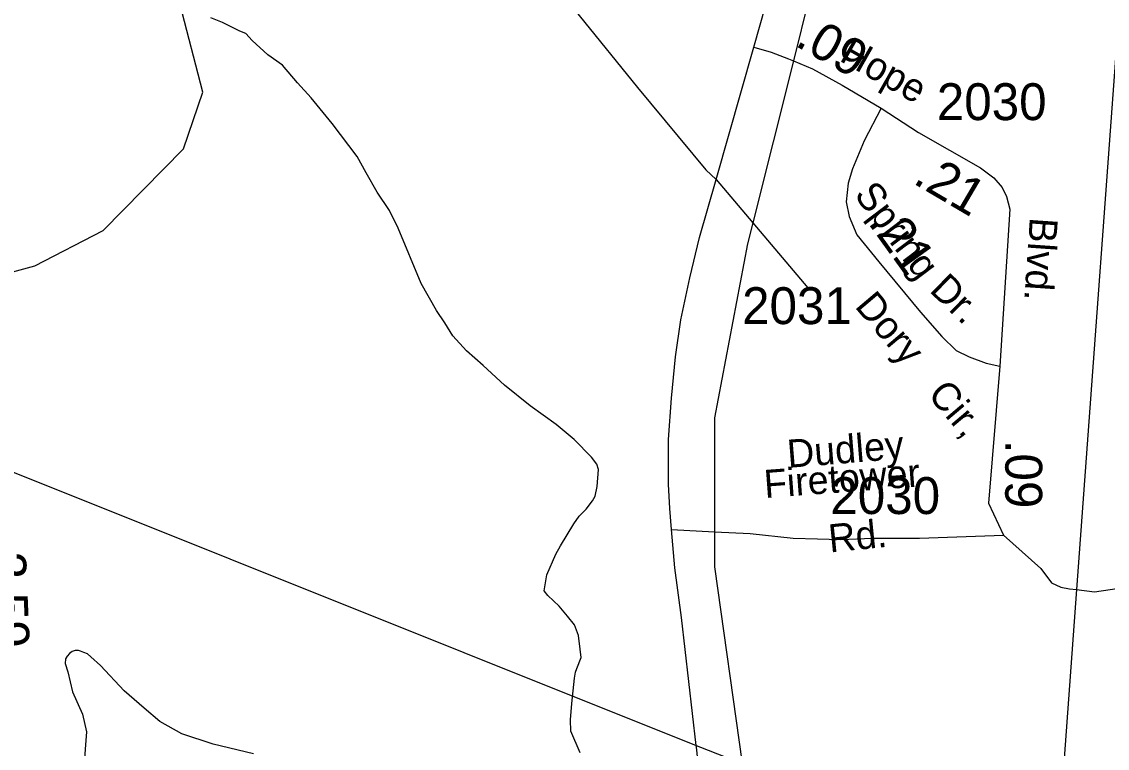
# Model space of a CAD drawing. Extents: x 2206922 to 2357709, y 510027 to 673830.
# Drawn here: x 2284540 to 2288216, y 564319 to 566780 of the extents above; entities that cross this region are included whole.
import ezdxf

# ---------------------------------------------------------------- set-up
doc = ezdxf.new("R2010")
doc.units = 0
for name, color, linetype in [('Exist Boundary Political Urban Extension UEB', 7, 'Continuous'), ('Exist Hydrographic Creek Single Shore', 7, 'Continuous'), ('Exist Hydrographic Misc Water Feature', 7, 'Continuous'), ('Exist Railroad Mainline', 7, 'Continuous'), ('Exist Road Non-System Type 51', 7, 'Continuous'), ('Exist Road Non-System Type 51 Label', 7, 'Continuous'), ('Exist Road Primary US Attributed', 7, 'Continuous'), ('Exist Road Primary US Mileage Hundredths English Label', 7, 'Continuous'), ('Exist Road Secondary Mileage Hundredths English Label', 7, 'Continuous'), ('Exist Road Secondary Type 51 Attributed', 7, 'Continuous'), ('Exist Road Secondary Type 51 Label', 7, 'Continuous'), ('Exist Road Secondary Type 51 Number Label', 7, 'Continuous'), ('Exist Utilities Electrical Transmission Line', 7, 'Continuous')]:
    doc.layers.add(name, color=color, linetype=linetype)

msp = doc.modelspace()

# ---------------------------------------------------------------- linework, layer by layer
at = {"layer": 'Exist Boundary Political Urban Extension UEB'}
for p, q in [((2287255.6, 567057.4), (2287153.1, 566647.3)), ((2287153.1, 566647.3), (2287015.8, 566098.4))]:
    msp.add_line(p, q, dxfattribs=at)
for points in [[(2287015.8, 566098.4), (2286997.9, 566026.9), (2286885.9, 565438.5), (2286885.9, 565052.4)], [(2286885.9, 565052.4), (2286885.9, 564934.1), (2286979.2, 564267.7)]]:
    msp.add_lwpolyline(points, dxfattribs=at)
at = {"layer": 'Exist Hydrographic Creek Single Shore'}
msp.add_lwpolyline([(2284267.9, 565867.3), (2284583.9, 565952.8), (2284815.8, 566072.7), (2285087.9, 566349.2), (2285152.9, 566541.4), (2285074.8, 566841.4), (2284622.9, 567145.7), (2284546.8, 567245.7), (2284511.9, 567393.9), (2284584.9, 567602.4), (2284716.8, 567786.6), (2285051.8, 568416.1), (2285341.8, 568610.2), (2286260.8, 569116.4), (2286583.8, 569362.4), (2286847.9, 569612.9), (2287119.8, 569968.2), (2287160, 570075.5)], dxfattribs=at)
at = {"layer": 'Exist Hydrographic Misc Water Feature'}
msp.add_lwpolyline([(2286430.6, 564303.6), (2286399.8, 564377.2), (2286397.8, 564415.2), (2286402.7, 564471.2), (2286411.9, 564557), (2286415.6, 564577.1), (2286419.9, 564589.1), (2286433.9, 564627.1), (2286431.2, 564655), (2286424.8, 564701), (2286412.1, 564737), (2286388.1, 564766.5), (2286359.8, 564800.4), (2286321.5, 564836.2), (2286309.2, 564851.8), (2286318.6, 564906), (2286348.2, 564976.2), (2286363.9, 565004.6), (2286409.1, 565078.9), (2286427.1, 565105), (2286451.1, 565129), (2286472.4, 565157.4), (2286482.3, 565173.3), (2286488, 565205.3), (2286493.3, 565263.3), (2286487.4, 565281.2), (2286469.3, 565305), (2286410.7, 565364.5), (2286350, 565415.8), (2286261.6, 565479.1), (2286174.9, 565548.5), (2286102.3, 565615.4), (2286045.9, 565664.8), (2285999.4, 565716.4), (2285972.9, 565760.2), (2285944.6, 565802.2), (2285891.9, 565893.6), (2285814.2, 566080.5), (2285785.5, 566140.4), (2285743, 566202), (2285706.3, 566267.5), (2285675.6, 566323.2), (2285590.9, 566434.5), (2285520, 566521.4), (2285473.6, 566573), (2285423.2, 566632.5), (2285373.1, 566668), (2285320.6, 566715.7), (2285298.3, 566739.4), (2285277.8, 566747.3), (2285220, 566776.7), (2285180, 566792.5)], dxfattribs=at)
at = {"layer": 'Exist Railroad Mainline'}
msp.add_lwpolyline([(2288952.5, 575417.9), (2288939.4, 575328.9), (2288894.6, 575010.5), (2288861, 574754.3), (2288832.1, 574422.3), (2288797.4, 574086.4), (2288738.9, 573282.2), (2288399.4, 568789.4), (2288395.5, 568735.1), (2288273, 567057.4), (2288112.4, 564856.3), (2288039.1, 563851.4), (2288038, 563836.6), (2287853.8, 561437.5), (2287845.7, 561332.3), (2287845.6, 561330.8)], dxfattribs=at)
at = {"layer": 'Exist Road Non-System Type 51'}
for p, q in [((2286891.3, 566245.8), (2287015.8, 566098.4)), ((2287015.8, 566098.4), (2287201.8, 565878.3)), ((2286740.1, 565060), (2286885.9, 565052.4))]:
    msp.add_line(p, q, dxfattribs=at)
for points in [[(2286229.7, 567046), (2286625.6, 566557), (2286857.1, 566278), (2286891.3, 566245.8)], [(2286885.9, 565052.4), (2287006.4, 565046.2), (2287152.4, 565030.4), (2287235.3, 565028.4), (2287314.2, 565026.4), (2287420.8, 565030.4), (2287580.6, 565030.4), (2287864.7, 565041.2)], [(2287864.7, 565041.2), (2287991.7, 564928.2), (2288027.2, 564878.9), (2288058.8, 564865.1), (2288088.4, 564859.1), (2288112.4, 564856.3)], [(2288112.4, 564856.3), (2288173.2, 564849.3), (2288416.1, 564885.6)], [(2285324.2, 564300.5), (2285188.1, 564333), (2285081.6, 564368.6), (2285007.6, 564410), (2284954.3, 564454.5), (2284886.2, 564513.7), (2284806.3, 564599.5), (2284773.8, 564629.2), (2284761.9, 564638.5), (2284750.1, 564643.9), (2284738.8, 564648.3), (2284731.5, 564650.3), (2284720.2, 564650.3), (2284709.9, 564646.3), (2284701.5, 564640.4), (2284693.2, 564631.6), (2284687.3, 564621.8), (2284686.3, 564606.5), (2284695.2, 564577.6), (2284711.8, 564510.3), (2284745.7, 564434.2), (2284759, 564374.5), (2284750.1, 564256.1)]]:
    msp.add_lwpolyline(points, dxfattribs=at)
at = {"layer": 'Exist Road Primary US Attributed'}
for points in [[(2287018.9, 566693.9), (2287122, 567057.4), (2287159.7, 567190.1), (2287281, 567619.5), (2287342.7, 567854), (2287396.4, 568031.7), (2287443.8, 568215.9), (2287480.6, 568403.5), (2287496.4, 568528.5), (2287500.3, 568606.2), (2287505.6, 568701.6), (2287512.2, 568832.5)], [(2287157.1, 561422.2), (2287066.4, 562197.1), (2286976.8, 562970.4), (2286888.1, 563740.3), (2286824.9, 564322.7), (2286824.2, 564328.7), (2286773.6, 564761.9), (2286751.9, 564929.7), (2286740.1, 565060), (2286734.2, 565131.1), (2286730.2, 565214), (2286730.2, 565365), (2286740.1, 565505.2), (2286753.9, 565645.3), (2286771.6, 565769.7), (2286801.9, 565912.8), (2286834.8, 566049), (2286891.3, 566245.8), (2287018.9, 566693.9)]]:
    msp.add_lwpolyline(points, dxfattribs=at)
at = {"layer": 'Exist Road Secondary Type 51 Attributed'}
for points in [[(2287018.9, 566693.9), (2287078.1, 566676.8), (2287136, 566654.4), (2287153.1, 566647.3), (2287217.5, 566620.2), (2287318.8, 566564.9), (2287450.4, 566487.3)], [(2287450.4, 566487.3), (2287392.5, 566376.1), (2287353, 566281.3), (2287338.6, 566232.6), (2287332, 566170.1), (2287342.5, 566120.1), (2287367.5, 566058.2), (2287442.5, 565966.1)], [(2287450.4, 566487.3), (2287576.6, 566405), (2287787.1, 566285.3), (2287831.8, 566251), (2287860.7, 566218.1), (2287875.2, 566187.9), (2287885.7, 566144.4), (2287852.8, 565612.8)], [(2287442.5, 565966.1), (2287583.2, 565795.7), (2287655.5, 565714.1), (2287704.2, 565666.7), (2287748.9, 565644.3), (2287805.5, 565623.3), (2287852.8, 565612.8)], [(2287852.8, 565612.8), (2287814.2, 565149.3), (2287864.7, 565041.2)]]:
    msp.add_lwpolyline(points, dxfattribs=at)
at = {"layer": 'Exist Utilities Electrical Transmission Line'}
msp.add_line((2284408.7, 565295), (2286824.2, 564328.7), dxfattribs=at)
msp.add_lwpolyline([(2286824.2, 564328.7), (2286838.2, 564323.1), (2286979.2, 564267.7)], dxfattribs=at)

# ---------------------------------------------------------------- texts
at = {"layer": 'Exist Road Non-System Type 51 Label'}
for s, rotation, p in [('Dory', 310.2474, (2287358.4, 565814.8)), ('Cir,', 310.2474, (2287604.8, 565515.5)), ('Dudley', 4.6306, (2287135.7, 565268.7)), ('Firetower', 4.2833, (2287056.9, 565166.4)), ('Rd.', 5.7188, (2287276.7, 564982))]:
    msp.add_text(s, height=95, rotation=rotation, dxfattribs=at).set_placement(p)
at = {"layer": 'Exist Road Primary US Mileage Hundredths English Label'}
msp.add_text('3.59', height=125, rotation=272.4728, dxfattribs=at).set_placement((2284428.3, 564980.9))
at = {"layer": 'Exist Road Secondary Mileage Hundredths English Label'}
for s, rotation, p in [('.09', 330.4605, (2287154.8, 566700.4)), ('.21', 329.5368, (2287554.2, 566234.6)), ('.21', 305.7473, (2287403.3, 566099.5)), ('.09', 269.9265, (2287870.9, 565364.1))]:
    msp.add_text(s, height=125, rotation=rotation, dxfattribs=at).set_placement(p)
at = {"layer": 'Exist Road Secondary Type 51 Label'}
for s, rotation, p in [('Hope', 330.4605, (2287305.2, 566649.3)), ('Spring', 307.1268, (2287356.2, 566192.6)), ('Blvd.', 266.0851, (2287954.2, 566118.8)), ('Dr.', 315.5533, (2287610.8, 565867.7))]:
    msp.add_text(s, height=95, rotation=rotation, dxfattribs=at).set_placement(p)
at = {"layer": 'Exist Road Secondary Type 51 Number Label'}
for s, p in [('2030', (2287638.8, 566446.3)), ('2031', (2286979.3, 565755.5)), ('2030', (2287278.2, 565112.4))]:
    msp.add_text(s, height=125, dxfattribs=at).set_placement(p)

doc.saveas('drawing.dxf')
